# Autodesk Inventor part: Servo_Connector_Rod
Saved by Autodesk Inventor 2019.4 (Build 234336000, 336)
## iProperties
Created: 2020-04
Part Number: Servo_Connector_Rod
Material: Generic
Document SubType Name: Modeling
Designer: Administrator
Density: 1 g/cm^3
Appearance: Default
Title: Servo_Connector_Rod v1
Author: Administrator
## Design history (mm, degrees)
feature "Body1"
body "Solid1"
